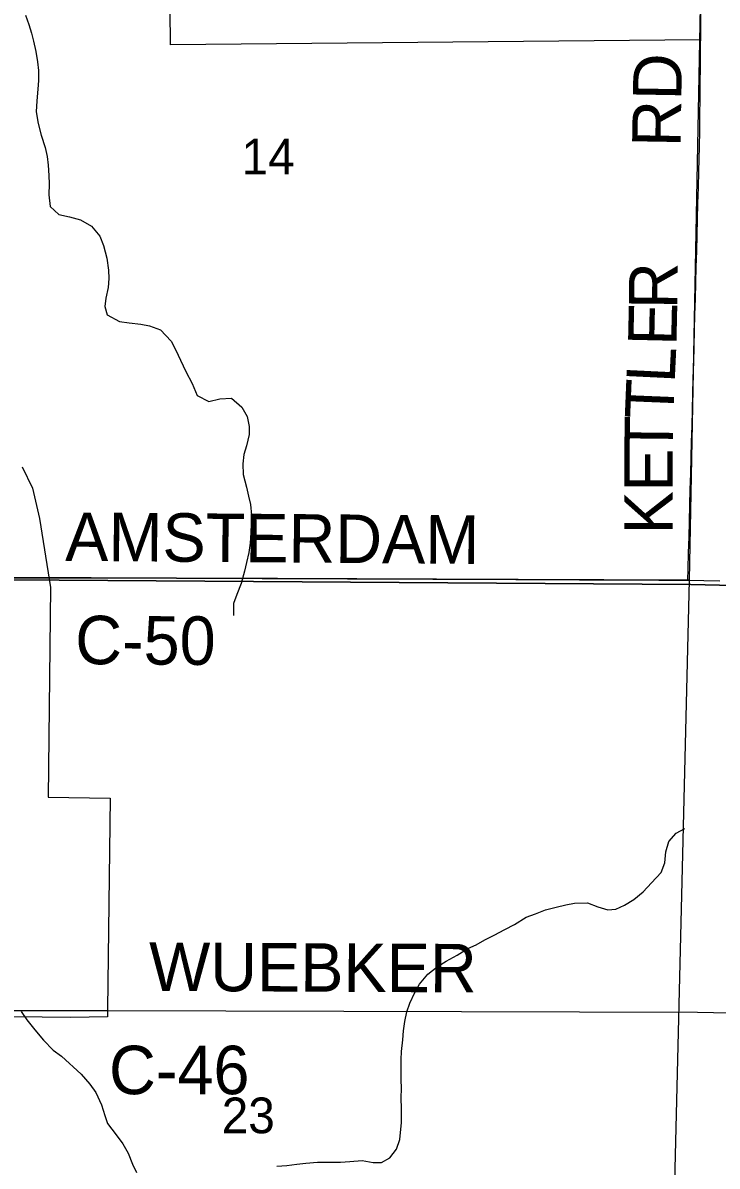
# Model space of a CAD drawing. Extents: x 0 to 34, y 0 to 22.
# Drawn here: x 5.988 to 6.802, y 15.728 to 17.068 of the extents above; entities that cross this region are included whole.
import ezdxf

# ---------------------------------------------------------------- set-up
doc = ezdxf.new("R2010")
doc.units = 0
for name, color, linetype in [('GM_X_Corporation', 7, 'Continuous'), ('GM_X_County_Road', 7, 'Continuous'), ('GM_X_County_Road_Text', 7, 'Continuous'), ('GM_X_Minor_River', 7, 'Continuous'), ('GM_X_Section_Text', 7, 'Continuous'), ('GM_X_Township_Road', 7, 'Continuous'), ('GM_X_Township_Road_Text', 7, 'Continuous')]:
    doc.layers.add(name, color=color, linetype=linetype)

msp = doc.modelspace()

# ---------------------------------------------------------------- linework, layer by layer
at = {"layer": 'GM_X_Corporation'}
for points in [[(5.7831, 17.4286), (6.7891, 17.4339), (6.7694, 16.4145), (5.7675, 16.4186)], [(5.7675, 16.4186), (6.7694, 16.4145), (6.7449, 15.4031), (5.7454, 15.4068)]]:
    msp.add_lwpolyline(points, close=True, dxfattribs=at)
for points in [[(6.7822, 17.1268), (6.7822, 17.048), (6.1613, 17.0421), (6.1606, 17.1246)], [(5.9876, 16.5475), (5.9997, 16.5224), (6.0078, 16.4871), (6.0205, 16.4062), (6.0178, 16.1601), (6.0905, 16.1589), (6.0874, 15.9117), (6.0874, 15.9026), (6.0446, 15.9021), (5.9093, 15.9035)], [(4.2697, 16.4379), (4.8738, 16.4249), (4.894, 16.4245), (5.045, 16.4217), (5.0523, 16.4215), (5.0651, 16.4213), (5.28, 16.4182), (5.4285, 16.4168), (5.6885, 16.4169), (6.7715, 16.4096), (7.7624, 16.3866)], [(7.7624, 16.3866), (6.7715, 16.4096), (5.6885, 16.4169), (5.4285, 16.4168), (5.28, 16.4182), (5.0651, 16.4213), (5.0523, 16.4215), (5.045, 16.4217), (4.894, 16.4245), (4.8738, 16.4249), (4.2697, 16.4379)]]:
    msp.add_lwpolyline(points, dxfattribs=at)
at = {"layer": 'GM_X_County_Road'}
for p, q in [((6.0252, 16.4173), (6.2757, 16.4168)), ((6.082, 15.9101), (6.088, 15.9101))]:
    msp.add_line(p, q, dxfattribs=at)
for points in [[(5.5788, 16.4201), (5.5947, 16.4199), (5.6106, 16.4197), (5.6292, 16.4195), (5.6479, 16.4192), (5.6665, 16.419), (5.6786, 16.4188), (5.691, 16.4187), (5.7097, 16.4184), (5.7283, 16.4182), (5.747, 16.418), (5.7581, 16.4178), (5.7693, 16.4177), (5.9112, 16.4175), (6.0252, 16.4173)], [(6.2757, 16.4168), (6.2867, 16.4168), (6.3054, 16.4167), (6.324, 16.4167), (6.3426, 16.4166), (6.3613, 16.4165), (6.3799, 16.4164), (6.3986, 16.4163), (6.4172, 16.4163), (6.4358, 16.4162), (6.4545, 16.4161), (6.4731, 16.416), (6.4918, 16.4159), (6.5104, 16.4158), (6.529, 16.4157), (6.5477, 16.4157), (6.5663, 16.4156), (6.585, 16.4155), (6.6036, 16.4154), (6.6223, 16.4153), (6.6409, 16.4152), (6.6595, 16.4152), (6.6782, 16.4151), (6.6968, 16.415), (6.7155, 16.4149), (6.7341, 16.4148), (6.751, 16.4147), (6.768, 16.4147), (6.7866, 16.4142), (6.8053, 16.4137)], [(5.8111, 15.9103), (5.9177, 15.9102), (6.082, 15.9101)], [(6.088, 15.9101), (6.7793, 15.9083), (6.798, 15.9079), (6.8166, 15.9074)]]:
    msp.add_lwpolyline(points, dxfattribs=at)
at = {"layer": 'GM_X_Minor_River'}
for points in [[(5.9915, 17.077), (5.9953, 17.0659), (5.9985, 17.0559), (6.0009, 17.0464), (6.0036, 17.0345), (6.0056, 17.0223), (6.0065, 17.012), (6.0066, 17.0006), (6.0059, 16.9904), (6.0048, 16.9767), (6.0037, 16.9638), (6.0064, 16.9501), (6.0098, 16.9363), (6.0144, 16.9217), (6.0168, 16.9114), (6.018, 16.9011), (6.0189, 16.8889), (6.019, 16.8794), (6.0187, 16.8665), (6.0202, 16.8528), (6.0306, 16.8434), (6.043, 16.8404), (6.0558, 16.837), (6.0689, 16.8298), (6.0785, 16.8178), (6.0828, 16.8071), (6.0866, 16.7922), (6.0888, 16.778), (6.089, 16.7681), (6.0883, 16.7579), (6.0857, 16.7454), (6.0843, 16.7356), (6.0871, 16.7256), (6.1017, 16.7177), (6.113, 16.7162), (6.1267, 16.7147), (6.1369, 16.7129), (6.1496, 16.7081), (6.1622, 16.6948), (6.1676, 16.6844), (6.173, 16.6725), (6.1795, 16.6594), (6.1867, 16.6452)], [(6.1867, 16.6452), (6.1928, 16.6313), (6.2063, 16.6241), (6.2192, 16.6272), (6.2329, 16.628), (6.2452, 16.6174), (6.2513, 16.6066), (6.2537, 16.5948), (6.2538, 16.5853), (6.2504, 16.5721), (6.2475, 16.5619), (6.2461, 16.5509), (6.2465, 16.5384), (6.2503, 16.5235), (6.2527, 16.5131), (6.2551, 16.5032), (6.2563, 16.491), (6.256, 16.4808), (6.2554, 16.4702), (6.2547, 16.458), (6.2532, 16.447), (6.2506, 16.4353), (6.2481, 16.4251), (6.2443, 16.4108), (6.239, 16.3977), (6.2354, 16.3871), (6.2354, 16.3731)], [(6.7455, 16.1084), (6.7541, 16.1181), (6.7645, 16.1235)], [(6.2859, 15.7275), (6.2977, 15.7283), (6.3095, 15.7299), (6.3201, 15.7312), (6.3338, 15.7323), (6.346, 15.7324), (6.3608, 15.7324), (6.3718, 15.7329), (6.3862, 15.7344), (6.3991, 15.7318), (6.4089, 15.7319), (6.4186, 15.7373), (6.4264, 15.7474), (6.4301, 15.759), (6.4322, 15.7787), (6.4322, 15.7943), (6.4318, 15.8083), (6.4321, 15.8182), (6.432, 15.8296), (6.432, 15.8421), (6.4319, 15.8527), (6.4321, 15.8622), (6.4336, 15.8759), (6.4346, 15.8861), (6.4361, 15.8974), (6.4386, 15.9084), (6.4419, 15.9189), (6.448, 15.9313), (6.4532, 15.941), (6.463, 15.9529), (6.4742, 15.9613), (6.4846, 15.9679), (6.4973, 15.9748), (6.51, 15.9828), (6.5196, 15.9871), (6.53, 15.9929), (6.5408, 15.9983), (6.5535, 16.0052), (6.5646, 16.011), (6.5785, 16.0197), (6.5892, 16.0236), (6.6011, 16.0283), (6.6137, 16.0314), (6.6248, 16.0341), (6.6351, 16.0361), (6.6503, 16.0365), (6.6623, 16.0316), (6.674, 16.0283), (6.6835, 16.0288), (6.6935, 16.0335), (6.7046, 16.0404), (6.7155, 16.0492), (6.7252, 16.0596), (6.7366, 16.0718), (6.741, 16.0831), (6.7421, 16.0963), (6.7455, 16.1084)], [(5.9864, 15.9088), (5.993, 15.8991), (6.0022, 15.8875), (6.0125, 15.8755), (6.0239, 15.8638), (6.0336, 15.8567), (6.0566, 15.8356), (6.0669, 15.8236), (6.0738, 15.8139), (6.0803, 15.7997), (6.0845, 15.787), (6.0877, 15.7775), (6.0976, 15.7643), (6.1053, 15.7539), (6.1118, 15.7427), (6.1168, 15.73), (6.1214, 15.72)]]:
    msp.add_lwpolyline(points, dxfattribs=at)
at = {"layer": 'GM_X_Township_Road'}
msp.add_line((6.7829, 17.0432), (6.783, 17.0504), dxfattribs=at)
for points in [[(6.783, 17.0504), (6.7831, 17.0618), (6.7833, 17.0804), (6.7835, 17.0991), (6.7836, 17.1128), (6.7838, 17.1265), (6.784, 17.1452), (6.7841, 17.1549), (6.7842, 17.1646), (6.7843, 17.1723)], [(6.768, 16.4147), (6.7683, 16.4278), (6.7688, 16.4465), (6.7693, 16.4651), (6.7698, 16.4838), (6.7703, 16.5024), (6.7708, 16.521), (6.7713, 16.5397), (6.7718, 16.5583), (6.7723, 16.5769), (6.7728, 16.5956), (6.7733, 16.6142), (6.7738, 16.6328), (6.7743, 16.6515), (6.7748, 16.6701), (6.7753, 16.6887), (6.7758, 16.7074), (6.7763, 16.726), (6.7768, 16.7446), (6.7773, 16.7633), (6.7778, 16.7819), (6.7783, 16.8005), (6.7788, 16.8192), (6.7793, 16.8378), (6.7798, 16.8564), (6.7803, 16.8751), (6.7808, 16.8937), (6.7812, 16.9083), (6.7816, 16.9229), (6.7818, 16.9415), (6.782, 16.9602), (6.7822, 16.9788), (6.7824, 16.9974), (6.7826, 17.0161), (6.7827, 17.0296), (6.7829, 17.0432)]]:
    msp.add_lwpolyline(points, dxfattribs=at)

# ---------------------------------------------------------------- texts
at = {"layer": 'GM_X_County_Road_Text'}
for s, rotation, p in [('AMSTERDAM', 359.5692, (6.0378, 16.4373)), ('C-50', 359.6571, (6.0495, 16.3162)), ('WUEBKER', 359.722, (6.1361, 15.9331)), ('C-46', 0, (6.0893, 15.812))]:
    msp.add_text(s, height=0.05682, rotation=rotation, dxfattribs=at).set_placement(p)
at = {"layer": 'GM_X_Section_Text'}
for s, p in [('14', (6.2447, 16.8903)), ('23', (6.2214, 15.7662))]:
    msp.add_text(s, height=0.04186, rotation=0, dxfattribs=at).set_placement(p)
at = {"layer": 'GM_X_Township_Road_Text'}
for s, height, rotation, p in [('RD', 0.05682, 89.0118, (6.7593, 16.922)), ('R', 0.0568, 89.4159, (6.7555, 16.7322)), ('E', 0.0568, 88.7202, (6.7545, 16.689)), ('L', 0.0568, 87.254, (6.7524, 16.645)), ('T', 0.0568, 87.6422, (6.7507, 16.6026)), ('T', 0.0568, 89.3164, (6.7502, 16.5606)), ('E', 0.0568, 89.9764, (6.7501, 16.5183)), ('K', 0.0568, 90, (6.7501, 16.4683))]:
    msp.add_text(s, height=height, rotation=rotation, dxfattribs=at).set_placement(p)

doc.saveas('drawing.dxf')
